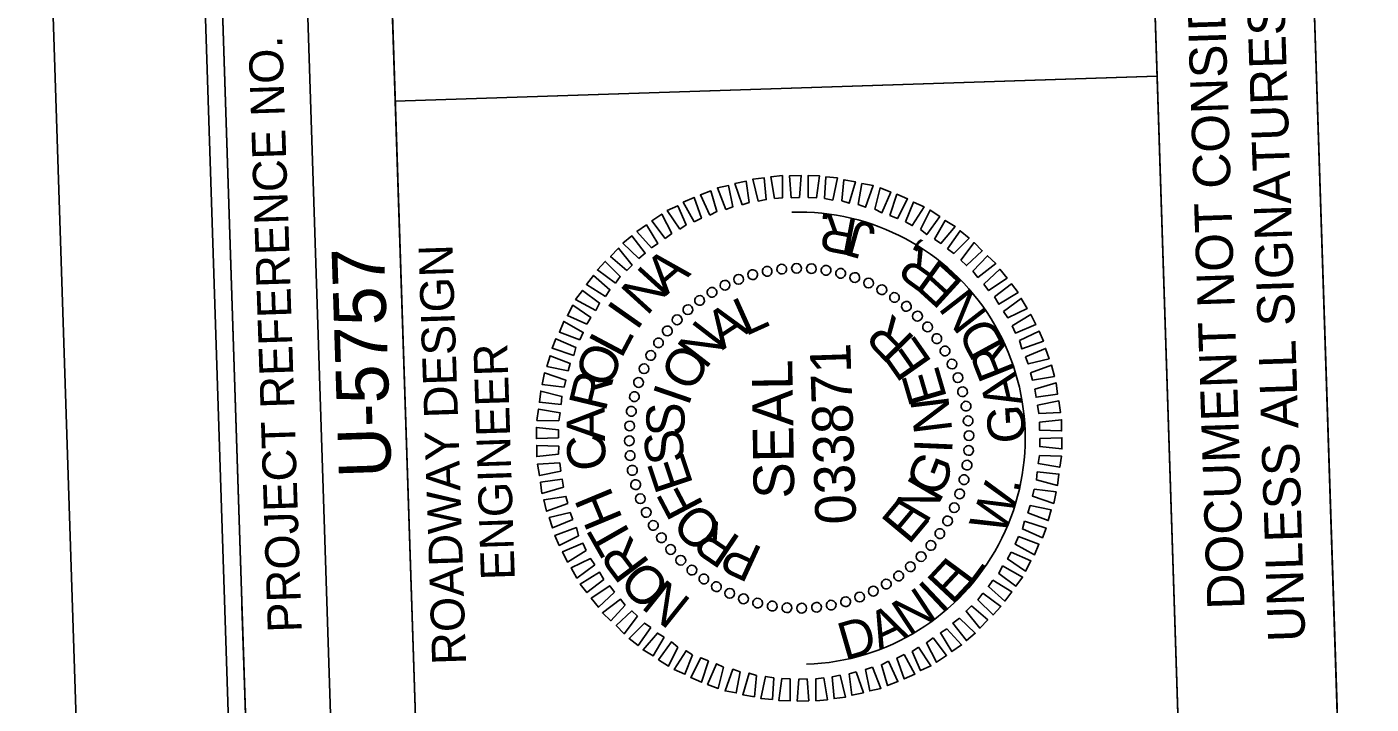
# Model space of a CAD drawing. Extents: x 1627318 to 1628473, y 762308 to 764226.
# Drawn here: x 1627317.6 to 1627516, y 763787.3 to 763887.2 of the extents above; entities that cross this region are included whole.
import ezdxf

# ---------------------------------------------------------------- set-up
doc = ezdxf.new("R2010")
doc.units = 0
for name, color, linetype in [('Old_Level_2', 7, 'Continuous'), ('Scratch_Level_0', 7, 'Continuous'), ('Sheet Data Field CELL', 7, 'Continuous'), ('Sheet Plot Border Inside CELL', 7, 'Continuous'), ('Sheet Plot Border Outside CELL', 7, 'Continuous'), ('Sheet Professional Seal CELL', 7, 'Continuous'), ('Sheet Profile CELL', 7, 'Continuous'), ('Sheet Profile Grid Major CELL', 7, 'Continuous'), ('Sheet Profile Grid Minor CELL', 7, 'Continuous'), ('Sheet Sticker Exception Certification CELL', 7, 'Continuous')]:
    doc.layers.add(name, color=color, linetype=linetype)

msp = doc.modelspace()

# ---------------------------------------------------------------- linework, layer by layer
at = {"layer": 'Old_Level_2'}
msp.add_lwpolyline([(1627511.12, 763780.74), (1627504.58, 763980.62), (1627568.5, 763982.71), (1627575.04, 763782.83)], close=True, dxfattribs=at)
at = {"layer": 'Scratch_Level_0'}
msp.add_arc((1627431.54, 763826.49), 33.36, 271.8735, 91.8735, dxfattribs=at)
at = {"layer": 'Sheet Plot Border Inside CELL'}
msp.add_lwpolyline([(1628449.68, 762356.66), (1628395.2, 764022.27), (1627340.66, 763987.77), (1627395.14, 762322.16)], close=True, dxfattribs=at)
at = {"layer": 'Sheet Plot Border Outside CELL'}
msp.add_lwpolyline([(1628472.54, 762344.4), (1628416.96, 764043.49), (1627317.55, 764007.53), (1627373.13, 762308.44)], close=True, dxfattribs=at)
at = {"layer": 'Sheet Professional Seal CELL'}
for p, q in [((1627424.64, 763850.63), (1627424.64, 763850.63)), ((1627426.83, 763851.1), (1627426.83, 763851.1)), ((1627428.97, 763851.47), (1627428.97, 763851.47)), ((1627431.17, 763851.6), (1627431.17, 763851.6)), ((1627433.37, 763851.52), (1627433.37, 763851.52)), ((1627435.53, 763851.24), (1627435.53, 763851.24)), ((1627437.64, 763850.86), (1627437.64, 763850.86)), ((1627420.59, 763849.1), (1627420.59, 763849.1)), ((1627422.56, 763849.96), (1627422.56, 763849.96)), ((1627439.77, 763850.23), (1627439.77, 763850.23)), ((1627441.79, 763849.39), (1627441.79, 763849.39)), ((1627443.78, 763848.46), (1627443.78, 763848.46)), ((1627416.81, 763846.82), (1627416.81, 763846.82)), ((1627418.68, 763848.04), (1627418.68, 763848.04)), ((1627445.62, 763847.27), (1627445.62, 763847.27)), ((1627415.11, 763845.52), (1627415.11, 763845.52)), ((1627447.41, 763845.97), (1627447.41, 763845.97)), ((1627449.01, 763844.53), (1627449.01, 763844.53)), ((1627412.06, 763842.37), (1627412.06, 763842.37)), ((1627413.51, 763843.96), (1627413.51, 763843.96)), ((1627450.56, 763842.93), (1627450.56, 763842.93)), ((1627410.77, 763840.57), (1627410.77, 763840.57)), ((1627451.87, 763841.22), (1627451.87, 763841.22)), ((1627409.57, 763838.73), (1627409.57, 763838.73)), ((1627453.08, 763839.36), (1627453.08, 763839.36)), ((1627408.64, 763836.75), (1627408.64, 763836.75)), ((1627454.14, 763837.44), (1627454.14, 763837.44)), ((1627407.8, 763834.72), (1627407.8, 763834.72)), ((1627455.01, 763835.47), (1627455.01, 763835.47)), ((1627407.17, 763832.6), (1627407.17, 763832.6)), ((1627455.67, 763833.39), (1627455.67, 763833.39)), ((1627406.79, 763830.49), (1627406.79, 763830.49)), ((1627456.15, 763831.2), (1627456.15, 763831.2)), ((1627456.52, 763829.06), (1627456.52, 763829.06)), ((1627406.51, 763828.33), (1627406.51, 763828.33)), ((1627431.54, 763826.49), (1627431.54, 763826.49)), ((1627456.64, 763826.87), (1627456.64, 763826.87)), ((1627406.44, 763826.12), (1627406.44, 763826.12)), ((1627456.56, 763824.66), (1627456.56, 763824.66)), ((1627406.56, 763823.93), (1627406.56, 763823.93)), ((1627456.28, 763822.5), (1627456.28, 763822.5)), ((1627406.93, 763821.79), (1627406.93, 763821.79)), ((1627407.4, 763819.6), (1627407.4, 763819.6)), ((1627455.9, 763820.39), (1627455.9, 763820.39)), ((1627408.07, 763817.52), (1627408.07, 763817.52)), ((1627455.27, 763818.27), (1627455.27, 763818.27)), ((1627408.93, 763815.55), (1627408.93, 763815.55)), ((1627454.43, 763816.24), (1627454.43, 763816.24)), ((1627410, 763813.63), (1627410, 763813.63)), ((1627453.5, 763814.26), (1627453.5, 763814.26)), ((1627411.21, 763811.77), (1627411.21, 763811.77)), ((1627451.02, 763810.62), (1627451.02, 763810.62)), ((1627452.31, 763812.42), (1627452.31, 763812.42)), ((1627412.51, 763810.06), (1627412.51, 763810.06)), ((1627449.57, 763809.03), (1627449.57, 763809.03)), ((1627414.07, 763808.46), (1627414.07, 763808.46)), ((1627415.66, 763807.02), (1627415.66, 763807.02)), ((1627447.97, 763807.47), (1627447.97, 763807.47)), ((1627417.46, 763805.72), (1627417.46, 763805.72)), ((1627444.4, 763804.95), (1627444.4, 763804.95)), ((1627446.26, 763806.17), (1627446.26, 763806.17)), ((1627419.3, 763804.53), (1627419.3, 763804.53)), ((1627421.28, 763803.6), (1627421.28, 763803.6)), ((1627423.31, 763802.76), (1627423.31, 763802.76)), ((1627440.51, 763803.03), (1627440.51, 763803.03)), ((1627442.48, 763803.89), (1627442.48, 763803.89)), ((1627425.43, 763802.13), (1627425.43, 763802.13)), ((1627427.54, 763801.75), (1627427.54, 763801.75)), ((1627429.7, 763801.47), (1627429.7, 763801.47)), ((1627431.91, 763801.39), (1627431.91, 763801.39)), ((1627434.1, 763801.52), (1627434.1, 763801.52)), ((1627436.24, 763801.89), (1627436.24, 763801.89)), ((1627438.43, 763802.36), (1627438.43, 763802.36))]:
    msp.add_line(p, q, dxfattribs=at)
for points in [[(1627423.11, 763860.94), (1627422.05, 763864.06), (1627423.74, 763864.41), (1627424.15, 763861.27)], [(1627425.49, 763861.47), (1627424.68, 763864.69), (1627426.38, 763864.9), (1627426.68, 763861.71)], [(1627427.88, 763861.84), (1627427.37, 763865.08), (1627429.07, 763865.24), (1627429.08, 763861.98)], [(1627430.38, 763861.98), (1627430.12, 763865.22), (1627431.82, 763865.27), (1627431.58, 763862.02)], [(1627432.88, 763862.01), (1627432.87, 763865.26), (1627434.52, 763865.21), (1627434.08, 763861.95)], [(1627435.28, 763861.84), (1627435.48, 763865.04), (1627437.18, 763864.9), (1627436.49, 763861.63)], [(1627437.84, 763861.52), (1627438.14, 763864.63), (1627439.85, 763864.34), (1627438.91, 763861.15)], [(1627418.35, 763859.38), (1627416.96, 763862.39), (1627418.49, 763862.99), (1627419.39, 763859.92)], [(1627420.73, 763860.26), (1627419.47, 763863.42), (1627421.11, 763863.77), (1627421.76, 763860.64)], [(1627440.26, 763860.95), (1627440.81, 763864.07), (1627442.47, 763863.77), (1627441.33, 763860.58)], [(1627442.69, 763860.28), (1627443.49, 763863.41), (1627445.06, 763862.81), (1627443.76, 763859.76)], [(1627444.92, 763859.35), (1627445.97, 763862.49), (1627447.54, 763861.79), (1627446.04, 763858.89)], [(1627413.92, 763857.34), (1627412.08, 763860.08), (1627413.61, 763860.78), (1627414.85, 763857.97)], [(1627416.04, 763858.41), (1627414.44, 763861.3), (1627416.02, 763862.01), (1627417.12, 763858.94)], [(1627447.25, 763858.43), (1627448.41, 763861.32), (1627449.98, 763860.62), (1627448.22, 763857.86)], [(1627411.76, 763855.96), (1627409.78, 763858.55), (1627411.25, 763859.55), (1627412.74, 763856.7)], [(1627449.44, 763857.3), (1627450.85, 763860.14), (1627452.28, 763859.19), (1627450.36, 763856.53)], [(1627451.49, 763855.86), (1627453.1, 763858.62), (1627454.58, 763857.71), (1627452.46, 763855.24)], [(1627407.86, 763853.03), (1627405.53, 763855.26), (1627406.85, 763856.35), (1627408.83, 763853.77)], [(1627409.76, 763854.6), (1627407.58, 763856.98), (1627409, 763857.97), (1627410.69, 763855.23)], [(1627453.44, 763854.43), (1627455.3, 763857.09), (1627456.63, 763856.03), (1627454.36, 763853.76)], [(1627406.11, 763851.23), (1627403.7, 763853.3), (1627404.86, 763854.54), (1627406.89, 763852)], [(1627455.39, 763852.74), (1627457.36, 763855.35), (1627458.55, 763854.14), (1627456.22, 763851.97)], [(1627404.42, 763849.37), (1627401.76, 763851.33), (1627402.92, 763852.57), (1627405.14, 763850.34)], [(1627457.19, 763851.15), (1627459.32, 763853.42), (1627460.56, 763852.26), (1627457.93, 763850.22)], [(1627402.94, 763847.42), (1627400.13, 763849.18), (1627401.19, 763850.52), (1627403.61, 763848.39)], [(1627458.81, 763849.2), (1627461.14, 763851.43), (1627462.23, 763850.11), (1627459.49, 763848.27)], [(1627401.51, 763845.32), (1627398.55, 763846.98), (1627399.56, 763848.31), (1627402.07, 763846.44)], [(1627460.37, 763847.35), (1627462.86, 763849.28), (1627463.85, 763848.01), (1627461.01, 763846.27)], [(1627461.69, 763845.19), (1627464.33, 763847.13), (1627465.18, 763845.61), (1627462.32, 763844.26)], [(1627400.22, 763843.33), (1627397.33, 763844.59), (1627398.13, 763846.11), (1627400.79, 763844.3)], [(1627462.96, 763843.08), (1627465.71, 763844.77), (1627466.46, 763843.25), (1627463.45, 763842)], [(1627399.15, 763840.99), (1627396.16, 763842.15), (1627396.8, 763843.72), (1627399.66, 763842.11)], [(1627464.08, 763840.92), (1627466.94, 763842.31), (1627467.59, 763840.83), (1627464.42, 763839.68)], [(1627398.27, 763838.71), (1627395.08, 763839.76), (1627395.64, 763841.18), (1627398.58, 763839.87)], [(1627397.44, 763836.44), (1627394.32, 763837.08), (1627394.77, 763838.65), (1627397.76, 763837.5)], [(1627464.96, 763838.49), (1627467.92, 763839.74), (1627468.42, 763838.21), (1627465.35, 763837.46)], [(1627465.69, 763836.12), (1627468.8, 763837.27), (1627469.21, 763835.58), (1627465.97, 763835.08)], [(1627396.87, 763834.02), (1627393.61, 763834.41), (1627393.95, 763836.12), (1627397.09, 763835.07)], [(1627466.32, 763833.74), (1627469.49, 763834.64), (1627469.69, 763833), (1627466.51, 763832.54)], [(1627396.41, 763831.45), (1627393.19, 763831.79), (1627393.39, 763833.45), (1627396.52, 763832.65)], [(1627396.08, 763829.04), (1627392.83, 763829.13), (1627393.08, 763830.79), (1627396.25, 763830.24)], [(1627466.7, 763831.35), (1627469.88, 763832), (1627470.13, 763830.31), (1627466.89, 763830.15)], [(1627467.03, 763828.86), (1627470.27, 763829.21), (1627470.27, 763827.56), (1627467.02, 763827.66)], [(1627396.02, 763826.53), (1627392.77, 763826.43), (1627392.76, 763828.08), (1627396.03, 763827.73)], [(1627467.06, 763826.46), (1627470.31, 763826.56), (1627470.31, 763824.91), (1627467.05, 763825.26)], [(1627396.04, 763824.13), (1627392.8, 763823.78), (1627392.8, 763825.43), (1627396.06, 763825.33)], [(1627396.38, 763821.64), (1627393.2, 763820.99), (1627392.94, 763822.68), (1627396.19, 763822.84)], [(1627466.99, 763823.95), (1627470.24, 763823.86), (1627470, 763822.2), (1627466.83, 763822.75)], [(1627466.67, 763821.54), (1627469.88, 763821.2), (1627469.68, 763819.54), (1627466.56, 763820.34)], [(1627396.75, 763819.25), (1627393.58, 763818.35), (1627393.38, 763819.99), (1627396.57, 763820.45)], [(1627466.2, 763818.97), (1627469.47, 763818.58), (1627469.12, 763816.87), (1627465.99, 763817.92)], [(1627397.38, 763816.87), (1627394.27, 763815.72), (1627393.86, 763817.41), (1627397.1, 763817.91)], [(1627465.63, 763816.55), (1627468.75, 763815.91), (1627468.3, 763814.34), (1627465.31, 763815.49)], [(1627398.11, 763814.5), (1627395.15, 763813.25), (1627394.65, 763814.78), (1627397.73, 763815.53)], [(1627398.99, 763812.07), (1627396.13, 763810.68), (1627395.49, 763812.16), (1627398.65, 763813.31)], [(1627464.8, 763814.28), (1627467.99, 763813.23), (1627467.44, 763811.81), (1627464.49, 763813.12)], [(1627400.11, 763809.91), (1627397.37, 763808.22), (1627396.62, 763809.74), (1627399.63, 763810.99)], [(1627463.93, 763812), (1627466.92, 763810.84), (1627466.27, 763809.27), (1627463.41, 763810.88)], [(1627401.38, 763807.8), (1627398.74, 763805.86), (1627397.89, 763807.38), (1627400.75, 763808.73)], [(1627462.85, 763809.66), (1627465.75, 763808.4), (1627464.95, 763806.88), (1627462.29, 763808.69)], [(1627402.7, 763805.64), (1627400.21, 763803.71), (1627399.22, 763804.98), (1627402.07, 763806.72)], [(1627461.57, 763807.67), (1627464.52, 763806.01), (1627463.52, 763804.68), (1627461, 763806.55)], [(1627404.26, 763803.79), (1627401.94, 763801.56), (1627400.84, 763802.88), (1627403.58, 763804.72)], [(1627460.14, 763805.57), (1627462.95, 763803.81), (1627461.89, 763802.47), (1627459.47, 763804.6)], [(1627405.88, 763801.84), (1627403.75, 763799.57), (1627402.51, 763800.73), (1627405.15, 763802.77)], [(1627458.65, 763803.62), (1627461.31, 763801.66), (1627460.15, 763800.42), (1627457.93, 763802.65)], [(1627407.68, 763800.25), (1627405.72, 763797.64), (1627404.53, 763798.85), (1627406.86, 763801.02)], [(1627456.96, 763801.76), (1627459.38, 763799.69), (1627458.22, 763798.45), (1627456.18, 763800.99)], [(1627409.64, 763798.56), (1627407.77, 763795.9), (1627406.44, 763796.96), (1627408.72, 763799.23)], [(1627455.22, 763799.95), (1627457.54, 763797.73), (1627456.23, 763796.64), (1627454.24, 763799.22)], [(1627411.59, 763797.13), (1627409.98, 763794.37), (1627408.49, 763795.27), (1627410.62, 763797.75)], [(1627451.31, 763797.03), (1627453.3, 763794.44), (1627451.83, 763793.44), (1627450.33, 763796.29)], [(1627453.32, 763798.39), (1627455.5, 763796.01), (1627454.08, 763795.02), (1627452.39, 763797.76)], [(1627413.63, 763795.69), (1627412.23, 763792.85), (1627410.79, 763793.8), (1627412.71, 763796.46)], [(1627415.82, 763794.56), (1627414.67, 763791.67), (1627413.09, 763792.37), (1627414.85, 763795.13)], [(1627449.15, 763795.65), (1627450.99, 763792.91), (1627449.47, 763792.21), (1627448.22, 763795.02)], [(1627418.15, 763793.64), (1627417.11, 763790.5), (1627415.53, 763791.2), (1627417.04, 763794.1)], [(1627420.39, 763792.71), (1627419.59, 763789.58), (1627418.02, 763790.18), (1627419.32, 763793.23)], [(1627442.35, 763792.73), (1627443.6, 763789.57), (1627441.96, 763789.22), (1627441.31, 763792.35)], [(1627444.72, 763793.61), (1627446.12, 763790.6), (1627444.59, 763790), (1627443.69, 763793.07)], [(1627447.04, 763794.58), (1627448.63, 763791.69), (1627447.06, 763790.98), (1627445.96, 763794.05)], [(1627422.81, 763792.04), (1627422.26, 763788.92), (1627420.6, 763789.22), (1627421.75, 763792.41)], [(1627425.23, 763791.47), (1627424.93, 763788.36), (1627423.22, 763788.65), (1627424.17, 763791.84)], [(1627427.79, 763791.15), (1627427.59, 763787.95), (1627425.89, 763788.09), (1627426.58, 763791.36)], [(1627430.2, 763790.98), (1627430.2, 763787.73), (1627428.55, 763787.78), (1627428.99, 763791.04)], [(1627432.7, 763791.01), (1627432.95, 763787.77), (1627431.25, 763787.72), (1627431.5, 763790.97)], [(1627435.19, 763791.15), (1627435.7, 763787.91), (1627434, 763787.75), (1627434, 763791.01)], [(1627437.58, 763791.52), (1627438.39, 763788.3), (1627436.69, 763788.09), (1627436.39, 763791.28)], [(1627439.97, 763792.05), (1627441.02, 763788.93), (1627439.33, 763788.58), (1627438.93, 763791.72)]]:
    msp.add_lwpolyline(points, close=True, dxfattribs=at)
for centre, major_axis in [((1627431.15, 763851.57), (-0.011, 0.72)), ((1627433.34, 763851.51), (0.052, 0.718)), ((1627422.6, 763849.93), (-0.257, 0.673)), ((1627424.68, 763850.62), (-0.197, 0.693)), ((1627426.81, 763851.12), (-0.136, 0.707)), ((1627428.97, 763851.44), (-0.074, 0.716)), ((1627435.51, 763851.26), (0.114, 0.711)), ((1627437.66, 763850.82), (0.176, 0.698)), ((1627439.75, 763850.19), (0.236, 0.68)), ((1627418.67, 763848.02), (-0.369, 0.618)), ((1627420.59, 763849.06), (-0.314, 0.648)), ((1627441.79, 763849.38), (0.294, 0.657)), ((1627443.74, 763848.4), (0.35, 0.629)), ((1627415.12, 763845.46), (-0.471, 0.544)), ((1627416.84, 763846.82), (-0.422, 0.583)), ((1627445.61, 763847.26), (0.404, 0.596)), ((1627447.36, 763845.95), (0.454, 0.559)), ((1627413.53, 763843.96), (-0.517, 0.501)), ((1627449, 763844.5), (0.501, 0.517)), ((1627412.08, 763842.32), (-0.559, 0.454)), ((1627450.5, 763842.91), (0.544, 0.471)), ((1627410.78, 763840.57), (-0.596, 0.404)), ((1627451.86, 763841.19), (0.583, 0.422)), ((1627409.63, 763838.7), (-0.629, 0.35)), ((1627453.06, 763839.36), (0.618, 0.369)), ((1627408.65, 763836.75), (-0.657, 0.294)), ((1627454.1, 763837.44), (0.648, 0.314)), ((1627407.84, 763834.71), (-0.68, 0.236)), ((1627454.97, 763835.43), (0.673, 0.257)), ((1627407.22, 763832.62), (-0.698, 0.176)), ((1627455.66, 763833.35), (0.693, 0.197)), ((1627406.77, 763830.47), (-0.711, 0.114)), ((1627456.17, 763831.23), (0.707, 0.136)), ((1627406.52, 763828.3), (-0.718, 0.052)), ((1627456.48, 763829.06), (0.716, 0.074)), ((1627406.46, 763826.11), (-0.72, -0.011)), ((1627456.61, 763826.88), (0.72, 0.011)), ((1627406.59, 763823.93), (-0.716, -0.074)), ((1627456.55, 763824.69), (0.718, -0.052)), ((1627406.91, 763821.76), (-0.707, -0.136)), ((1627456.3, 763822.52), (0.711, -0.114)), ((1627455.86, 763820.37), (0.698, -0.176)), ((1627407.41, 763819.64), (-0.693, -0.197)), ((1627455.23, 763818.28), (0.68, -0.236)), ((1627408.1, 763817.56), (-0.673, -0.257)), ((1627454.43, 763816.24), (0.657, -0.294)), ((1627408.97, 763815.55), (-0.648, -0.314)), ((1627453.45, 763814.29), (0.629, -0.35)), ((1627410.01, 763813.63), (-0.618, -0.369)), ((1627411.21, 763811.8), (-0.583, -0.422)), ((1627452.3, 763812.42), (0.596, -0.404)), ((1627412.57, 763810.08), (-0.544, -0.471)), ((1627450.99, 763810.67), (0.559, -0.454)), ((1627414.07, 763808.49), (-0.501, -0.517)), ((1627449.54, 763809.03), (0.517, -0.501)), ((1627415.71, 763807.04), (-0.454, -0.559)), ((1627446.23, 763806.17), (0.422, -0.583)), ((1627447.95, 763807.53), (0.471, -0.544)), ((1627417.47, 763805.73), (-0.404, -0.596)), ((1627419.33, 763804.59), (-0.35, -0.629)), ((1627442.48, 763803.93), (0.314, -0.648)), ((1627444.41, 763804.97), (0.369, -0.618)), ((1627421.29, 763803.61), (-0.294, -0.657)), ((1627423.32, 763802.8), (-0.236, -0.68)), ((1627425.42, 763802.17), (-0.176, -0.698)), ((1627436.27, 763801.87), (0.136, -0.707)), ((1627438.4, 763802.37), (0.197, -0.693)), ((1627440.47, 763803.06), (0.257, -0.673)), ((1627427.56, 763801.73), (-0.114, -0.711)), ((1627429.73, 763801.48), (-0.052, -0.718)), ((1627431.92, 763801.42), (0.011, -0.72)), ((1627434.1, 763801.55), (0.074, -0.716))]:
    msp.add_ellipse(centre, major_axis=major_axis, ratio=0.999708, dxfattribs=at)
at = {"layer": 'Sheet Profile CELL'}
for p, q in [((1627362.7, 763775.83), (1627356.16, 763975.77)), ((1627371.92, 763876.24), (1627484.31, 763879.91))]:
    msp.add_line(p, q, dxfattribs=at)
for points in [[(1627343.62, 763975.36), (1627392.66, 762476.17), (1628442.1, 762510.49), (1628393.06, 764009.69)], [(1627371.92, 763876.24), (1627368.66, 763976.18), (1627481.09, 763979.86), (1627484.36, 763879.91)], [(1627350.16, 763775.42), (1627343.62, 763975.36), (1627368.66, 763976.18), (1627375.2, 763776.24)], [(1627375.2, 763776.24), (1627371.92, 763876.24), (1627484.36, 763879.91), (1627487.64, 763779.92)]]:
    msp.add_lwpolyline(points, close=True, dxfattribs=at)
at = {"layer": 'Sheet Profile Grid Major CELL'}
msp.add_lwpolyline([(1627867.87, 763242.11), (1627866.24, 763292.08), (1627366.5, 763275.74), (1627364.87, 763325.71), (1627864.6, 763342.06), (1627862.97, 763392.03), (1627363.23, 763375.68), (1627361.6, 763425.66), (1627861.33, 763442), (1627859.7, 763491.98), (1627359.96, 763475.63), (1627358.33, 763525.6), (1627858.06, 763541.95), (1627856.43, 763591.92), (1627356.7, 763575.58), (1627355.06, 763625.55), (1627854.79, 763641.9), (1627853.16, 763691.87), (1627353.43, 763675.52), (1627351.79, 763725.5), (1627851.52, 763741.84), (1627849.89, 763791.82), (1627350.16, 763775.47), (1627349.3, 763801.76)], dxfattribs=at)
at = {"layer": 'Sheet Sticker Exception Certification CELL'}
for p, q in [((1627487.64, 763779.92), (1627481.1, 763979.85)), ((1627487.64, 763779.92), (1627481.1, 763979.85)), ((1627504.58, 763980.62), (1627511.12, 763780.69)), ((1627504.58, 763980.62), (1627511.12, 763780.69))]:
    msp.add_line(p, q, dxfattribs=at)

# ---------------------------------------------------------------- texts
at = {"layer": 'Sheet Data Field CELL'}
msp.add_text('U-5757', height=7.75, rotation=91.8735, dxfattribs=at).set_placement((1627371.37, 763820.77))
at = {"layer": 'Sheet Professional Seal CELL'}
for s, height, rotation, p in [('A', 5.64, 40.4906, (1627411.89, 763847.46)), ('N', 5.64, 47.6924, (1627409.04, 763844.42)), ('I', 5.64, 54.8936, (1627407.56, 763842.22)), ('L', 5.64, 24.2743, (1627423.59, 763841.49)), ('A', 5.64, 33.6337, (1627420.21, 763839.43)), ('R', 5.64, 134.3549, (1627448.82, 763841.17)), ('N', 5.64, 52.3501, (1627417.7, 763836.5)), ('L', 5.64, 62.0943, (1627405.29, 763838.09)), ('E', 5.64, 124.9976, (1627451.28, 763837.7)), ('O', 5.64, 69.2946, (1627403.59, 763833.64)), ('O', 5.64, 61.707, (1627415.81, 763833.08)), ('SEAL', 5.998, 90.8735, (1627430.83, 763817.62)), ('E', 5.64, 106.2852, (1627453.4, 763832.46)), ('R', 5.64, 76.4946, (1627402.95, 763830.26)), ('I', 5.64, 71.0631, (1627415.18, 763831.06)), ('A', 5.64, 90.8938, (1627402.89, 763826.06)), ('S', 5.64, 89.7739, (1627414.62, 763826.74)), ('N', 5.64, 96.9299, (1627454.16, 763827.54)), ('C', 5.64, 98.0933, (1627403.31, 763822.12)), ('S', 5.64, 99.1291, (1627414.79, 763823.15)), ('I', 5.64, 87.5747, (1627454.12, 763824.18)), ('E', 5.64, 108.4845, (1627415.95, 763819.73)), ('G', 5.64, 68.8637, (1627452.44, 763817.57)), ('N', 5.64, 59.5074, (1627450.31, 763813.7)), ('H', 5.64, 112.4929, (1627405.56, 763814.59)), ('F', 5.64, 117.8405, (1627417.55, 763816.58)), ('E', 5.64, 50.1504, (1627447.71, 763810.62)), ('O', 5.64, 136.5547, (1627420.61, 763813.38)), ('R', 5.64, 145.9131, (1627423.12, 763811.71)), ('T', 5.64, 119.6932, (1627407.32, 763811.4)), ('R', 5.64, 126.894, (1627409.63, 763808.07)), ('P', 5.64, 155.2724, (1627426.37, 763810.22)), ('O', 5.64, 134.0952, (1627412.84, 763804.72)), ('N', 5.64, 141.297, (1627415.81, 763802.52))]:
    msp.add_text(s, height=height, rotation=rotation, dxfattribs=at).set_placement(p)
at = {"layer": 'Sheet Profile CELL'}
for s, height, p in [('PROJECT REFERENCE NO.', 5.0001, (1627358.12, 763797.91)), ('ROADWAY DESIGN', 5.0001, (1627382.38, 763793.15)), ('ENGINEER', 5, (1627389.58, 763805.64))]:
    msp.add_text(s, height=height, rotation=91.8735, dxfattribs=at).set_placement(p)
at = {"layer": 'Sheet Profile Grid Minor CELL'}
for s, height, rotation, p in [('R', 5.5, 169.2275, (1627440.39, 763858.77)), ('.', 5.5, 176.154, (1627436.43, 763859.61)), ('J', 5.5, 164.359, (1627443.1, 763857.91)), ('R', 5.5, 144.2523, (1627453.19, 763852.02)), (',', 5.5, 151.1787, (1627449.95, 763854.44)), ('E', 5.5, 137.6693, (1627455.97, 763849.37)), ('N', 5.5, 127.7376, (1627459.55, 763844.81)), ('D', 5.5, 118.5929, (1627462.11, 763840.12)), ('R', 5.5, 111.6665, (1627463.53, 763836.34)), ('033871', 5.998, 91.8735, (1627439.96, 763813.87)), ('A', 5.5, 103.4807, (1627464.6, 763831.68)), ('G', 5.5, 93.549, (1627465, 763825.9)), ('W', 5.5, 68.7626, (1627461.67, 763811.93)), ('.', 5.5, 80.3687, (1627463.98, 763818.29)), ('E', 5.5, 46.9243, (1627454.09, 763801.76)), ('L', 5.5, 53.5073, (1627456.78, 763804.51)), ('I', 5.5, 43.4038, (1627452.53, 763800.43)), ('N', 5.5, 33.4721, (1627447.72, 763797.2)), ('A', 5.5, 25.2863, (1627443.38, 763795.19)), ('D', 5.5, 16.1417, (1627438.25, 763793.71))]:
    msp.add_text(s, height=height, rotation=rotation, dxfattribs=at).set_placement(p)
at = {"layer": 'Sheet Sticker Exception Certification CELL'}
for s, p in [('UNLESS ALL SIGNATURES COMPLETED', (1627506.25, 763796.53)), ('UNLESS ALL SIGNATURES COMPLETED', (1627506.25, 763796.53)), ('DOCUMENT NOT CONSIDERED FINAL', (1627497.29, 763801.32)), ('DOCUMENT NOT CONSIDERED FINAL', (1627497.29, 763801.32))]:
    msp.add_text(s, height=5.5, rotation=91.8735, dxfattribs=at).set_placement(p)

doc.saveas('drawing.dxf')
